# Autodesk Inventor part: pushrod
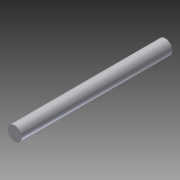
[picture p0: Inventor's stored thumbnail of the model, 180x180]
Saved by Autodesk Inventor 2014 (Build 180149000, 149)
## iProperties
Shininess: 64.0
Length Units: 11272
Angle Units: 11279
Time Units: 11290
Mass Units: 11286
Length Display Precision: 3
Angle Display Precision: 2
Compacted: True
Part Number: pushrod
Document SubType Name: Modeling
Created: 2003-01
Designer: dayb
Density: 1 g/cm^3
Mass: 14.3634 g
Surface Area: 50.1398 cm^2
Volume: 14.3634 cm^3
Material: Generic
Appearance: Default
Density: 0.0
Volumn: 0.0
Area: 0.0
PropertySet Name: Model Information
Control State: 0
Master: False
Checked Out: False
Author: dayb
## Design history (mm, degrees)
sketch "Sketch1"
  geometry: C1 r 6 at (0, -9.25) reference
  dimensions: "d0" = 127 dimension on C1.centre C1
extrude "Extrusion1" new body sketch "Sketch1" distance "d0" = 127; taper "d1" = 0 deg
body "Solid1"
node "Reference1"
